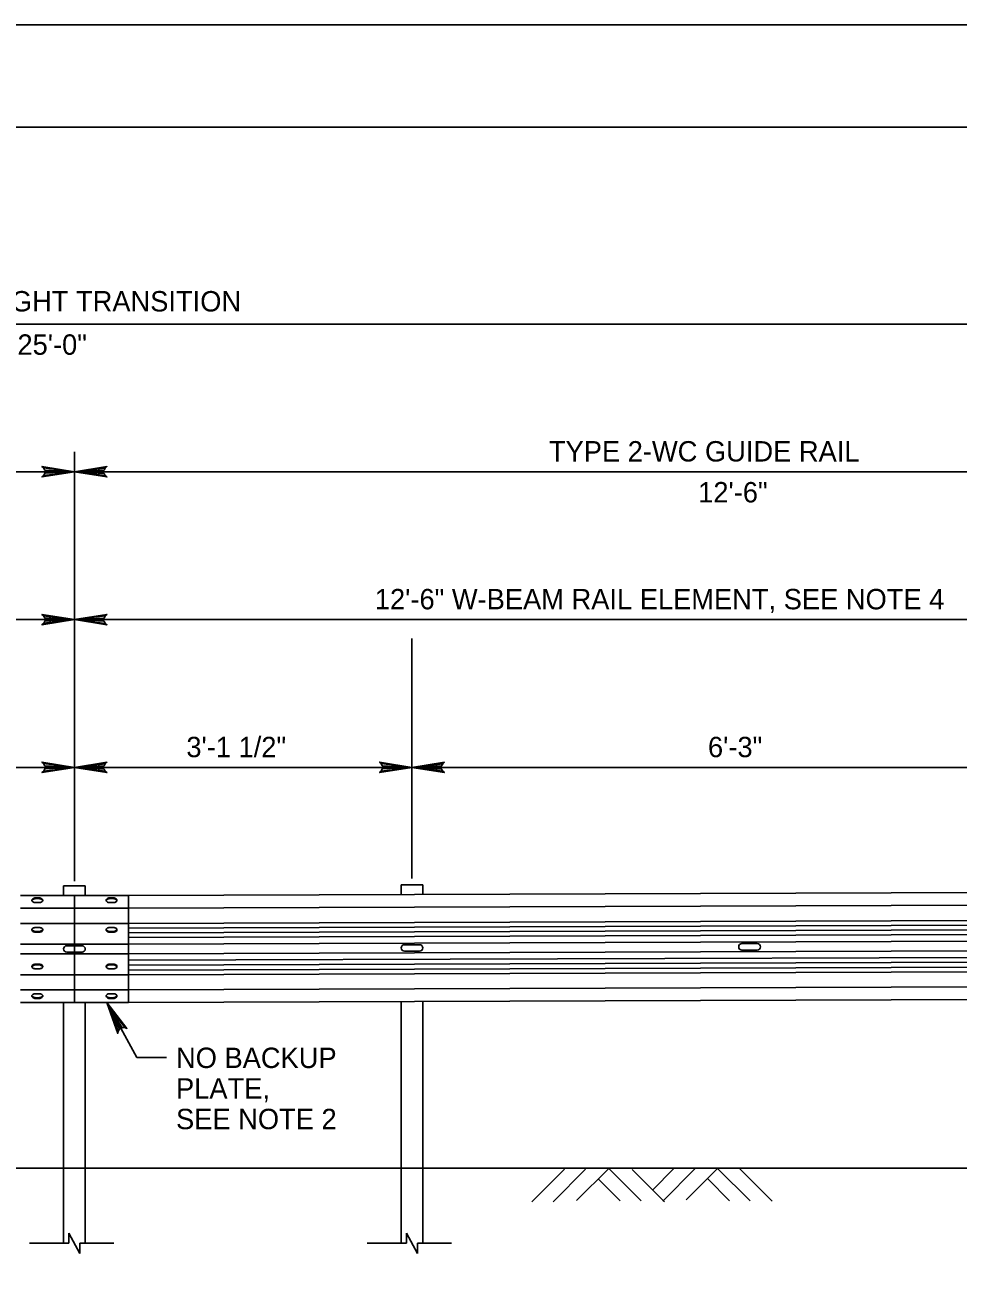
# Model space of a CAD drawing. Extents: x 637628 to 640188, y 298266 to 300751.
# Drawn here: x 639479 to 639616.3, y 299269.8 to 299453.6 of the extents above; entities that cross this region are included whole.
import ezdxf

# ---------------------------------------------------------------- set-up
doc = ezdxf.new("R2010")
doc.units = 0
for name, color, linetype in [('1', 7, 'Continuous'), ('2', 7, 'Continuous'), ('PLT-BNDY', 7, 'Continuous'), ('S-ABUT-CONC', 7, 'Continuous'), ('S-ANNO-CELL', 7, 'Continuous')]:
    doc.layers.add(name, color=color, linetype=linetype)

msp = doc.modelspace()

# ---------------------------------------------------------------- linework, layer by layer
at = {"layer": '1'}
msp.add_line((639494.26, 299309.75), (639494.26, 299325.48), dxfattribs=at)
msp.add_lwpolyline([(639945.52, 298874.58), (639945.52, 299438.55), (639159.55, 299438.55), (639159.55, 298874.58), (639945.52, 298874.58), (639945.52, 298900.93), (639745.53, 298900.93), (639745.53, 298965.61), (639945.52, 298965.61), (639945.52, 298994.57), (639745.53, 298994.57), (639745.53, 298874.58), (639824.33, 298874.58), (639824.33, 298900.93), (639824.33, 298874.58), (639901.33, 298874.58), (639901.33, 298900.93), (639901.33, 298888.62), (639945.52, 298888.62)], dxfattribs=at)
at = {"layer": '2'}
for p, q in [((639558.39, 299285.19), (639553.62, 299280.42)), ((639561.5, 299285.19), (639556.72, 299280.42)), ((639564.91, 299285.32), (639560.18, 299280.59)), ((639566.57, 299280.55), (639563.35, 299283.77)), ((639569.68, 299280.55), (639564.91, 299285.32)), ((639573.09, 299280.42), (639568.36, 299285.15)), ((639574.51, 299285.29), (639571.37, 299282.14)), ((639577.62, 299285.29), (639572.85, 299280.52)), ((639580.93, 299285.32), (639576.3, 299280.69)), ((639582.7, 299280.56), (639579.48, 299283.78)), ((639585.71, 299280.55), (639580.93, 299285.32)), ((639588.95, 299280.52), (639584.15, 299285.32))]:
    msp.add_line(p, q, dxfattribs=at)
for points in [[(639481.76, 299388.41), (639481.93, 299388.08), (639486.3, 299387.84), (639481.76, 299388.41), (639481.53, 299388.61), (639486.3, 299387.84), (639481.94, 299387.62), (639481.78, 299387.3), (639486.3, 299387.84), (639481.53, 299387.08), (639481.78, 299387.3)], [(639490.84, 299387.27), (639490.67, 299387.6), (639486.3, 299387.84), (639490.84, 299387.27), (639491.08, 299387.07), (639486.3, 299387.84), (639490.67, 299388.05), (639490.83, 299388.38), (639486.3, 299387.84), (639491.08, 299388.6), (639490.83, 299388.38)], [(639481.76, 299366.65), (639481.93, 299366.32), (639486.3, 299366.09), (639481.76, 299366.65), (639481.53, 299366.85), (639486.3, 299366.09), (639481.94, 299365.87), (639481.78, 299365.54), (639486.3, 299366.09), (639481.53, 299365.32), (639481.78, 299365.54)], [(639490.84, 299365.52), (639490.67, 299365.85), (639486.3, 299366.09), (639490.84, 299365.52), (639491.08, 299365.32), (639486.3, 299366.09), (639490.67, 299366.3), (639490.83, 299366.63), (639486.3, 299366.09), (639491.08, 299366.85), (639490.83, 299366.63)], [(639481.76, 299344.9), (639481.93, 299344.57), (639486.3, 299344.33), (639481.76, 299344.9), (639481.53, 299345.1), (639486.3, 299344.33), (639481.94, 299344.12), (639481.78, 299343.79), (639486.3, 299344.33), (639481.53, 299343.57), (639481.78, 299343.79)], [(639490.84, 299343.76), (639490.67, 299344.09), (639486.3, 299344.33), (639490.84, 299343.76), (639491.08, 299343.56), (639486.3, 299344.33), (639490.67, 299344.55), (639490.83, 299344.87), (639486.3, 299344.33), (639491.08, 299345.09), (639490.83, 299344.87)], [(639531.42, 299344.9), (639531.59, 299344.57), (639535.96, 299344.33), (639531.42, 299344.9), (639531.19, 299345.1), (639535.96, 299344.33), (639531.6, 299344.12), (639531.44, 299343.79), (639535.96, 299344.33), (639531.19, 299343.57), (639531.44, 299343.79)], [(639540.5, 299343.76), (639540.33, 299344.09), (639535.96, 299344.33), (639540.5, 299343.76), (639540.74, 299343.56), (639535.96, 299344.33), (639540.33, 299344.55), (639540.49, 299344.87), (639535.96, 299344.33), (639540.74, 299345.09), (639540.49, 299344.87)], [(639492.74, 299305.49), (639492.95, 299305.8), (639491.08, 299309.75), (639492.74, 299305.49), (639492.68, 299305.19), (639491.08, 299309.75), (639493.35, 299306.02), (639493.71, 299306.03), (639491.08, 299309.75), (639494.02, 299305.92), (639493.71, 299306.03)]]:
    msp.add_lwpolyline(points, dxfattribs=at)
at = {"layer": 'PLT-BNDY'}
msp.add_lwpolyline([(639119.52, 299453.58), (639960.52, 299453.58), (639960.52, 298859.58), (639119.52, 298859.58)], close=True, dxfattribs=at)
at = {"layer": 'S-ABUT-CONC'}
for p, q in [((639287.66, 299409.55), (639684.94, 299409.55)), ((639486.3, 299327.59), (639486.3, 299390.77)), ((639287.66, 299387.84), (639486.3, 299387.84)), ((639486.3, 299387.84), (639684.94, 299387.84)), ((639287.66, 299366.09), (639486.3, 299366.09)), ((639486.3, 299366.09), (639684.94, 299366.09)), ((639535.96, 299327.97), (639535.96, 299363.29)), ((639436.64, 299344.33), (639486.3, 299344.33)), ((639486.3, 299344.33), (639535.96, 299344.33)), ((639535.96, 299344.33), (639635.28, 299344.33)), ((639491.08, 299309.75), (639495.49, 299301.63)), ((639495.49, 299301.63), (639499.87, 299301.63))]:
    msp.add_line(p, q, dxfattribs=at)
at = {"layer": 'S-ANNO-CELL'}
for p, q in [((639487.89, 299326.88), (639484.71, 299326.88)), ((639484.71, 299325.48), (639484.71, 299326.88)), ((639487.89, 299325.48), (639487.89, 299326.88)), ((639676.99, 299326.12), (639494.26, 299325.48)), ((639537.55, 299327.03), (639534.37, 299327.03)), ((639534.37, 299325.62), (639534.37, 299327.03)), ((639537.55, 299325.63), (639537.55, 299327.03)), ((639494.26, 299325.48), (639478.35, 299325.48)), ((639480.69, 299325.14), (639481.01, 299325.14)), ((639480.69, 299325.03), (639480.69, 299325.14)), ((639481.01, 299325.03), (639480.69, 299325.03)), ((639480.69, 299324.43), (639481.01, 299324.43)), ((639481.01, 299325.03), (639481.01, 299325.14)), ((639486.3, 299309.88), (639486.3, 299325.48)), ((639491.6, 299325.14), (639491.92, 299325.14)), ((639491.6, 299325.03), (639491.6, 299325.14)), ((639491.92, 299325.03), (639491.6, 299325.03)), ((639491.6, 299324.43), (639491.92, 299324.43)), ((639491.92, 299325.03), (639491.92, 299325.14)), ((639676.99, 299324.27), (639494.26, 299323.63)), ((639494.26, 299323.63), (639478.35, 299323.63)), ((639494.26, 299321.37), (639478.35, 299321.37)), ((639480.69, 299320.78), (639481.01, 299320.78)), ((639491.6, 299320.78), (639491.92, 299320.78)), ((639676.99, 299322.01), (639494.26, 299321.37)), ((639676.99, 299321.32), (639494.26, 299320.68)), ((639676.99, 299320.63), (639494.26, 299320)), ((639480.69, 299320.18), (639480.69, 299320.07)), ((639481.01, 299320.18), (639480.69, 299320.18)), ((639480.69, 299320.07), (639481.01, 299320.07)), ((639481.01, 299320.18), (639481.01, 299320.07)), ((639491.6, 299320.18), (639491.6, 299320.07)), ((639491.92, 299320.18), (639491.6, 299320.18)), ((639491.6, 299320.07), (639491.92, 299320.07)), ((639491.92, 299320.18), (639491.92, 299320.07)), ((639676.99, 299319.95), (639494.26, 299319.31)), ((639676.99, 299318.95), (639494.26, 299318.31)), ((639494.26, 299318.31), (639478.35, 299318.31)), ((639494.26, 299316.91), (639478.35, 299316.91)), ((639486.3, 299318.09), (639485.19, 299318.09)), ((639486.3, 299317.14), (639485.19, 299317.14)), ((639487.42, 299318.09), (639486.3, 299318.09)), ((639487.42, 299317.14), (639486.3, 299317.14)), ((639676.99, 299317.55), (639494.26, 299316.91)), ((639535.96, 299318.24), (639534.85, 299318.24)), ((639535.96, 299318.24), (639534.85, 299318.24)), ((639535.96, 299317.28), (639534.85, 299317.28)), ((639535.96, 299317.28), (639534.85, 299317.28)), ((639537.08, 299318.24), (639535.96, 299318.24)), ((639537.08, 299318.24), (639535.96, 299318.24)), ((639537.08, 299317.28), (639535.96, 299317.28)), ((639537.08, 299317.28), (639535.96, 299317.28)), ((639585.62, 299318.41), (639584.51, 299318.41)), ((639585.62, 299317.45), (639584.51, 299317.45)), ((639586.74, 299318.41), (639585.62, 299318.41)), ((639586.74, 299317.45), (639585.62, 299317.45)), ((639480.69, 299315.39), (639481.01, 299315.39)), ((639480.69, 299315.28), (639480.69, 299315.39)), ((639481.01, 299315.28), (639480.69, 299315.28)), ((639481.01, 299315.28), (639481.01, 299315.39)), ((639491.6, 299315.39), (639491.92, 299315.39)), ((639491.6, 299315.28), (639491.6, 299315.39)), ((639491.92, 299315.28), (639491.6, 299315.28)), ((639491.92, 299315.28), (639491.92, 299315.39)), ((639676.99, 299316.56), (639494.26, 299315.95)), ((639676.99, 299315.87), (639494.26, 299315.23)), ((639676.99, 299315.14), (639494.26, 299314.5)), ((639494.26, 299313.82), (639478.35, 299313.82)), ((639480.69, 299314.68), (639481.01, 299314.68)), ((639491.6, 299314.68), (639491.92, 299314.68)), ((639676.99, 299314.45), (639494.26, 299313.82)), ((639494.26, 299311.6), (639478.35, 299311.6)), ((639676.99, 299312.24), (639494.26, 299311.6)), ((639494.26, 299309.75), (639478.35, 299309.75)), ((639480.69, 299311.03), (639481.01, 299311.03)), ((639480.69, 299310.43), (639480.69, 299310.32)), ((639481.01, 299310.43), (639480.69, 299310.43)), ((639480.69, 299310.32), (639481.01, 299310.32)), ((639481.01, 299310.43), (639481.01, 299310.32)), ((639484.71, 299285.33), (639484.71, 299309.75)), ((639487.89, 299285.33), (639487.89, 299309.75)), ((639491.6, 299311.03), (639491.92, 299311.03)), ((639491.6, 299310.43), (639491.6, 299310.32)), ((639491.92, 299310.43), (639491.6, 299310.43)), ((639491.6, 299310.32), (639491.92, 299310.32)), ((639491.92, 299310.43), (639491.92, 299310.32)), ((639676.99, 299310.39), (639494.26, 299309.75)), ((639534.37, 299285.33), (639534.37, 299309.89)), ((639537.55, 299285.33), (639537.55, 299309.9)), ((639238, 299285.33), (639581.11, 299285.33)), ((639484.71, 299285.33), (639484.71, 299274.31)), ((639487.89, 299285.33), (639487.89, 299274.31)), ((639534.37, 299285.33), (639534.37, 299274.31)), ((639537.55, 299285.33), (639537.55, 299274.31)), ((639581.11, 299285.33), (639895.3, 299285.33)), ((639485.48, 299274.31), (639485.48, 299275.81)), ((639487.12, 299272.81), (639485.48, 299275.81)), ((639535.14, 299274.31), (639535.14, 299275.81)), ((639536.78, 299272.81), (639535.14, 299275.81)), ((639479.71, 299274.31), (639483.94, 299274.31)), ((639480.48, 299274.31), (639485.48, 299274.31)), ((639487.12, 299274.31), (639487.12, 299272.81)), ((639487.12, 299274.31), (639492.12, 299274.31)), ((639529.37, 299274.31), (639533.6, 299274.31)), ((639530.14, 299274.31), (639535.14, 299274.31)), ((639536.78, 299274.31), (639536.78, 299272.81)), ((639536.78, 299274.31), (639541.78, 299274.31))]:
    msp.add_line(p, q, dxfattribs=at)
for points in [[(639480.69, 299324.43), (639480.58, 299324.43), (639480.47, 299324.45), (639480.37, 299324.47), (639480.28, 299324.51), (639480.2, 299324.55), (639480.14, 299324.6), (639480.09, 299324.66), (639480.06, 299324.72), (639480.05, 299324.78), (639480.06, 299324.84), (639480.09, 299324.9), (639480.14, 299324.96), (639480.2, 299325.01), (639480.28, 299325.05), (639480.37, 299325.09), (639480.47, 299325.12), (639480.58, 299325.13), (639480.69, 299325.14)], [(639480.69, 299325.03), (639480.58, 299325.02), (639480.47, 299325.01), (639480.37, 299324.98), (639480.28, 299324.94), (639480.2, 299324.9), (639480.14, 299324.85), (639480.09, 299324.79), (639480.06, 299324.73), (639480.06, 299324.73)], [(639481.01, 299325.14), (639481.12, 299325.13), (639481.22, 299325.12), (639481.32, 299325.09), (639481.41, 299325.05), (639481.49, 299325.01), (639481.56, 299324.96), (639481.6, 299324.9), (639481.63, 299324.84), (639481.64, 299324.78), (639481.63, 299324.72), (639481.6, 299324.66), (639481.56, 299324.6), (639481.49, 299324.55), (639481.41, 299324.51), (639481.32, 299324.47), (639481.22, 299324.45), (639481.12, 299324.43), (639481.01, 299324.43)], [(639481.63, 299324.73), (639481.63, 299324.73), (639481.6, 299324.79), (639481.56, 299324.85), (639481.49, 299324.9), (639481.41, 299324.94), (639481.32, 299324.98), (639481.22, 299325.01), (639481.12, 299325.02), (639481.01, 299325.03)], [(639491.6, 299324.43), (639491.49, 299324.43), (639491.38, 299324.45), (639491.28, 299324.47), (639491.19, 299324.51), (639491.11, 299324.55), (639491.05, 299324.6), (639491, 299324.66), (639490.97, 299324.72), (639490.96, 299324.78), (639490.97, 299324.84), (639491, 299324.9), (639491.05, 299324.96), (639491.11, 299325.01), (639491.19, 299325.05), (639491.28, 299325.09), (639491.38, 299325.12), (639491.49, 299325.13), (639491.6, 299325.14)], [(639491.6, 299325.03), (639491.49, 299325.02), (639491.38, 299325.01), (639491.28, 299324.98), (639491.19, 299324.94), (639491.11, 299324.9), (639491.05, 299324.85), (639491, 299324.79), (639490.97, 299324.73), (639490.97, 299324.73)], [(639491.92, 299325.14), (639492.03, 299325.13), (639492.14, 299325.12), (639492.24, 299325.09), (639492.33, 299325.05), (639492.41, 299325.01), (639492.47, 299324.96), (639492.52, 299324.9), (639492.55, 299324.84), (639492.56, 299324.78), (639492.55, 299324.72), (639492.52, 299324.66), (639492.47, 299324.6), (639492.41, 299324.55), (639492.33, 299324.51), (639492.24, 299324.47), (639492.14, 299324.45), (639492.03, 299324.43), (639491.92, 299324.43)], [(639492.55, 299324.73), (639492.55, 299324.73), (639492.52, 299324.79), (639492.47, 299324.85), (639492.41, 299324.9), (639492.33, 299324.94), (639492.24, 299324.98), (639492.14, 299325.01), (639492.03, 299325.02), (639491.92, 299325.03)], [(639480.69, 299320.78), (639480.58, 299320.78), (639480.47, 299320.76), (639480.37, 299320.74), (639480.28, 299320.7), (639480.2, 299320.66), (639480.14, 299320.61), (639480.09, 299320.55), (639480.06, 299320.49), (639480.05, 299320.43), (639480.06, 299320.37), (639480.09, 299320.31), (639480.14, 299320.25), (639480.2, 299320.2), (639480.28, 299320.15), (639480.37, 299320.12), (639480.47, 299320.09), (639480.58, 299320.08), (639480.69, 299320.07)], [(639480.69, 299320.18), (639480.58, 299320.19), (639480.47, 299320.2), (639480.37, 299320.23), (639480.28, 299320.26), (639480.2, 299320.31), (639480.14, 299320.36), (639480.09, 299320.42), (639480.06, 299320.48), (639480.06, 299320.48)], [(639481.01, 299320.07), (639481.12, 299320.08), (639481.22, 299320.09), (639481.32, 299320.12), (639481.41, 299320.15), (639481.49, 299320.2), (639481.56, 299320.25), (639481.6, 299320.31), (639481.63, 299320.37), (639481.64, 299320.43), (639481.63, 299320.49), (639481.6, 299320.55), (639481.56, 299320.61), (639481.49, 299320.66), (639481.41, 299320.7), (639481.32, 299320.74), (639481.22, 299320.76), (639481.12, 299320.78), (639481.01, 299320.78)], [(639481.63, 299320.48), (639481.63, 299320.48), (639481.6, 299320.42), (639481.56, 299320.36), (639481.49, 299320.31), (639481.41, 299320.26), (639481.32, 299320.23), (639481.22, 299320.2), (639481.12, 299320.19), (639481.01, 299320.18)], [(639491.6, 299320.78), (639491.49, 299320.78), (639491.38, 299320.76), (639491.28, 299320.74), (639491.19, 299320.7), (639491.11, 299320.66), (639491.05, 299320.61), (639491, 299320.55), (639490.97, 299320.49), (639490.96, 299320.43), (639490.97, 299320.37), (639491, 299320.31), (639491.05, 299320.25), (639491.11, 299320.2), (639491.19, 299320.15), (639491.28, 299320.12), (639491.38, 299320.09), (639491.49, 299320.08), (639491.6, 299320.07)], [(639491.6, 299320.18), (639491.49, 299320.19), (639491.38, 299320.2), (639491.28, 299320.23), (639491.19, 299320.26), (639491.11, 299320.31), (639491.05, 299320.36), (639491, 299320.42), (639490.97, 299320.48), (639490.97, 299320.48)], [(639491.92, 299320.07), (639492.03, 299320.08), (639492.14, 299320.09), (639492.24, 299320.12), (639492.33, 299320.15), (639492.41, 299320.2), (639492.47, 299320.25), (639492.52, 299320.31), (639492.55, 299320.37), (639492.56, 299320.43), (639492.55, 299320.49), (639492.52, 299320.55), (639492.47, 299320.61), (639492.41, 299320.66), (639492.33, 299320.7), (639492.24, 299320.74), (639492.14, 299320.76), (639492.03, 299320.78), (639491.92, 299320.78)], [(639492.55, 299320.48), (639492.55, 299320.48), (639492.52, 299320.42), (639492.47, 299320.36), (639492.41, 299320.31), (639492.33, 299320.26), (639492.24, 299320.23), (639492.14, 299320.2), (639492.03, 299320.19), (639491.92, 299320.18)], [(639480.69, 299314.68), (639480.58, 299314.68), (639480.47, 299314.7), (639480.37, 299314.72), (639480.28, 299314.76), (639480.2, 299314.8), (639480.14, 299314.85), (639480.09, 299314.91), (639480.06, 299314.97), (639480.05, 299315.03), (639480.06, 299315.09), (639480.09, 299315.15), (639480.14, 299315.21), (639480.2, 299315.26), (639480.28, 299315.3), (639480.37, 299315.34), (639480.47, 299315.37), (639480.58, 299315.38), (639480.69, 299315.39)], [(639480.69, 299315.28), (639480.58, 299315.27), (639480.47, 299315.26), (639480.37, 299315.23), (639480.28, 299315.19), (639480.2, 299315.15), (639480.14, 299315.1), (639480.09, 299315.04), (639480.06, 299314.98), (639480.06, 299314.98)], [(639481.01, 299315.39), (639481.12, 299315.38), (639481.22, 299315.37), (639481.32, 299315.34), (639481.41, 299315.3), (639481.49, 299315.26), (639481.56, 299315.21), (639481.6, 299315.15), (639481.63, 299315.09), (639481.64, 299315.03), (639481.63, 299314.97), (639481.6, 299314.91), (639481.56, 299314.85), (639481.49, 299314.8), (639481.41, 299314.76), (639481.32, 299314.72), (639481.22, 299314.7), (639481.12, 299314.68), (639481.01, 299314.68)], [(639481.63, 299314.98), (639481.63, 299314.98), (639481.6, 299315.04), (639481.56, 299315.1), (639481.49, 299315.15), (639481.41, 299315.19), (639481.32, 299315.23), (639481.22, 299315.26), (639481.12, 299315.27), (639481.01, 299315.28)], [(639491.6, 299314.68), (639491.49, 299314.68), (639491.38, 299314.7), (639491.28, 299314.72), (639491.19, 299314.76), (639491.11, 299314.8), (639491.05, 299314.85), (639491, 299314.91), (639490.97, 299314.97), (639490.96, 299315.03), (639490.97, 299315.09), (639491, 299315.15), (639491.05, 299315.21), (639491.11, 299315.26), (639491.19, 299315.3), (639491.28, 299315.34), (639491.38, 299315.37), (639491.49, 299315.38), (639491.6, 299315.39)], [(639491.6, 299315.28), (639491.49, 299315.27), (639491.38, 299315.26), (639491.28, 299315.23), (639491.19, 299315.19), (639491.11, 299315.15), (639491.05, 299315.1), (639491, 299315.04), (639490.97, 299314.98), (639490.97, 299314.98)], [(639491.92, 299315.39), (639492.03, 299315.38), (639492.14, 299315.37), (639492.24, 299315.34), (639492.33, 299315.3), (639492.41, 299315.26), (639492.47, 299315.21), (639492.52, 299315.15), (639492.55, 299315.09), (639492.56, 299315.03), (639492.55, 299314.97), (639492.52, 299314.91), (639492.47, 299314.85), (639492.41, 299314.8), (639492.33, 299314.76), (639492.24, 299314.72), (639492.14, 299314.7), (639492.03, 299314.68), (639491.92, 299314.68)], [(639492.55, 299314.98), (639492.55, 299314.98), (639492.52, 299315.04), (639492.47, 299315.1), (639492.41, 299315.15), (639492.33, 299315.19), (639492.24, 299315.23), (639492.14, 299315.26), (639492.03, 299315.27), (639491.92, 299315.28)], [(639480.69, 299311.03), (639480.58, 299311.03), (639480.47, 299311.01), (639480.37, 299310.99), (639480.28, 299310.95), (639480.2, 299310.91), (639480.14, 299310.86), (639480.09, 299310.8), (639480.06, 299310.74), (639480.05, 299310.68), (639480.06, 299310.62), (639480.09, 299310.56), (639480.14, 299310.5), (639480.2, 299310.45), (639480.28, 299310.4), (639480.37, 299310.37), (639480.47, 299310.34), (639480.58, 299310.33), (639480.69, 299310.32)], [(639480.69, 299310.43), (639480.58, 299310.44), (639480.47, 299310.45), (639480.37, 299310.48), (639480.28, 299310.51), (639480.2, 299310.56), (639480.14, 299310.61), (639480.09, 299310.67), (639480.06, 299310.73), (639480.06, 299310.73)], [(639481.01, 299310.32), (639481.12, 299310.33), (639481.22, 299310.34), (639481.32, 299310.37), (639481.41, 299310.4), (639481.49, 299310.45), (639481.56, 299310.5), (639481.6, 299310.56), (639481.63, 299310.62), (639481.64, 299310.68), (639481.63, 299310.74), (639481.6, 299310.8), (639481.56, 299310.86), (639481.49, 299310.91), (639481.41, 299310.95), (639481.32, 299310.99), (639481.22, 299311.01), (639481.12, 299311.03), (639481.01, 299311.03)], [(639481.63, 299310.73), (639481.63, 299310.73), (639481.6, 299310.67), (639481.56, 299310.61), (639481.49, 299310.56), (639481.41, 299310.51), (639481.32, 299310.48), (639481.22, 299310.45), (639481.12, 299310.44), (639481.01, 299310.43)], [(639491.6, 299311.03), (639491.49, 299311.03), (639491.38, 299311.01), (639491.28, 299310.99), (639491.19, 299310.95), (639491.11, 299310.91), (639491.05, 299310.86), (639491, 299310.8), (639490.97, 299310.74), (639490.96, 299310.68), (639490.97, 299310.62), (639491, 299310.56), (639491.05, 299310.5), (639491.11, 299310.45), (639491.19, 299310.4), (639491.28, 299310.37), (639491.38, 299310.34), (639491.49, 299310.33), (639491.6, 299310.32)], [(639491.6, 299310.43), (639491.49, 299310.44), (639491.38, 299310.45), (639491.28, 299310.48), (639491.19, 299310.51), (639491.11, 299310.56), (639491.05, 299310.61), (639491, 299310.67), (639490.97, 299310.73), (639490.97, 299310.73)], [(639491.92, 299310.32), (639492.03, 299310.33), (639492.14, 299310.34), (639492.24, 299310.37), (639492.33, 299310.4), (639492.41, 299310.45), (639492.47, 299310.5), (639492.52, 299310.56), (639492.55, 299310.62), (639492.56, 299310.68), (639492.55, 299310.74), (639492.52, 299310.8), (639492.47, 299310.86), (639492.41, 299310.91), (639492.33, 299310.95), (639492.24, 299310.99), (639492.14, 299311.01), (639492.03, 299311.03), (639491.92, 299311.03)], [(639492.55, 299310.73), (639492.55, 299310.73), (639492.52, 299310.67), (639492.47, 299310.61), (639492.41, 299310.56), (639492.33, 299310.51), (639492.24, 299310.48), (639492.14, 299310.45), (639492.03, 299310.44), (639491.92, 299310.43)]]:
    msp.add_lwpolyline(points, dxfattribs=at)
for centre, start, end in [((639485.19, 299317.61), 90, 270), ((639487.42, 299317.61), 270, 90), ((639534.85, 299317.76), 90, 270), ((639534.85, 299317.76), 90, 270), ((639537.08, 299317.76), 270, 90), ((639537.08, 299317.76), 270, 90), ((639584.51, 299317.93), 90, 270), ((639586.74, 299317.93), 270, 90)]:
    msp.add_arc(centre, 0.478, start, end, dxfattribs=at)

# ---------------------------------------------------------------- texts
at = {"layer": 'S-ABUT-CONC'}
for s, p in [('GUIDE RAIL HEIGHT TRANSITION', (639446.41, 299411.42)), ('25\'-0"', (639477.92, 299405.05)), ('TYPE 2-WC GUIDE RAIL', (639556.11, 299389.34)), ('12\'-6"', (639578.07, 299383.32)), ('12\'-6" W-BEAM RAIL ELEMENT, SEE NOTE 4', (639530.5, 299367.59)), ('3\'-1 1/2"', (639502.77, 299345.83)), ('6\'-3"', (639579.51, 299345.83)), ('NO BACKUP', (639501.25, 299300.09)), ('PLATE, ', (639501.25, 299295.59)), ('SEE NOTE 2', (639501.25, 299291.09))]:
    msp.add_text(s, height=3, dxfattribs=at).set_placement(p)

doc.saveas('drawing.dxf')
